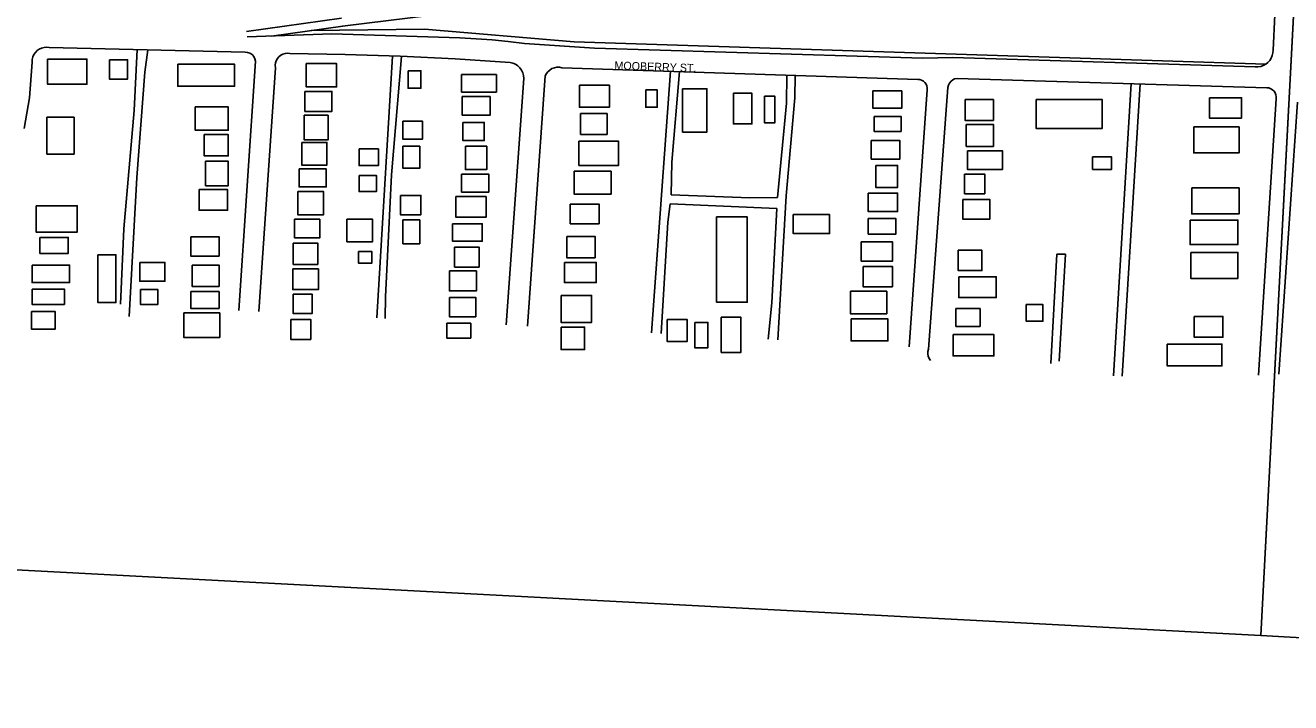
# Model space of a CAD drawing. Extents: x -9648 to 41057, y -12373 to 40276.
# Drawn here: x 15887 to 17468, y -6142 to -5297 of the extents above; entities that cross this region are included whole.
import ezdxf

# ---------------------------------------------------------------- set-up
doc = ezdxf.new("R2010")
doc.units = 0
doc.layers.add('SC_Scratch1', color=7, linetype='Continuous')
doc.layers.add('SH_Data', color=7, linetype='Continuous')

msp = doc.modelspace()

# ---------------------------------------------------------------- linework, layer by layer
at = {"layer": 'SC_Scratch1'}
for p, q in [((17431, -6058.5), (17512.2, -4520.7)), ((17512.2, -4520.7), (17431, -6058.5)), ((15846.2, -5974.8), (17431, -6058.5)), ((17431, -6058.5), (19015.8, -6142.2))]:
    msp.add_line(p, q, dxfattribs=at)
at = {"layer": 'SH_Data'}
for p, q in [((16506.5, -5270.2), (16283.5, -5297.6)), ((16282.3, -5287.7), (16163.3, -5304.3)), ((17446.1, -5327.7), (17448.5, -5283.5)), ((16164.3, -5311.1), (16270.1, -5307.3)), ((16283.7, -5297.6), (16194.8, -5310)), ((16385.7, -5301.6), (16244.2, -5303.1)), ((16270.1, -5307.3), (16430.1, -5312.1)), ((16573, -5317.2), (16385.7, -5301.6)), ((16430.1, -5312.1), (16450.3, -5313.3)), ((15902, -5328.2), (15904.6, -5326.4)), ((15904.6, -5326.4), (15907.5, -5325)), ((15907.5, -5325), (15910.7, -5324.1)), ((15910.7, -5324.1), (15913.9, -5323.8)), ((15913.9, -5323.8), (15917.1, -5324.1)), ((15917.1, -5324.1), (16161.7, -5330.3)), ((16026.7, -5326.9), (16023.3, -5402.9)), ((16036.5, -5354.9), (16040.3, -5327.2)), ((16450.3, -5313.3), (16470.5, -5314.9)), ((16470.5, -5314.9), (16490.6, -5316.8)), ((16490.6, -5316.8), (16510.7, -5319.1)), ((16510.7, -5319.1), (16598.5, -5325.1)), ((17436.9, -5345.1), (16573, -5317.2)), ((16598.5, -5325.1), (17008.7, -5337.5)), ((17445.9, -5331.1), (17446.1, -5327.7)), ((15892.5, -5387.1), (15895.5, -5342.5)), ((15895.5, -5342.5), (15895.7, -5339.3)), ((15895.7, -5339.3), (15896.5, -5336.1)), ((15896.5, -5336.1), (15897.9, -5333.2)), ((15897.9, -5333.2), (15899.7, -5330.5)), ((15899.7, -5330.5), (15902, -5328.2)), ((16174.7, -5341.3), (16154, -5652.6)), ((16161.7, -5330.3), (16164.8, -5330.5)), ((16164.8, -5330.5), (16167.8, -5331.5)), ((16167.8, -5331.5), (16170.4, -5333.2)), ((16170.4, -5333.2), (16172.5, -5335.5)), ((16172.5, -5335.5), (16174, -5338.3)), ((16174, -5338.3), (16174.7, -5341.3)), ((16199.5, -5346.5), (16199.8, -5343.6)), ((16199.8, -5343.6), (16200.7, -5340.8)), ((16200.7, -5340.8), (16202.2, -5338.2)), ((16202.2, -5338.2), (16204.1, -5335.9)), ((16204.1, -5335.9), (16206.4, -5334)), ((16206.4, -5334), (16209, -5332.6)), ((16209, -5332.6), (16211.8, -5331.8)), ((16211.8, -5331.8), (16214.7, -5331.5)), ((16214.7, -5331.5), (16217.7, -5331.7)), ((16217.7, -5331.7), (16286.6, -5333)), ((16286.6, -5333), (16355.4, -5335.3)), ((16345.9, -5335), (16326.5, -5661.9)), ((16344.7, -5483.1), (16357.1, -5335.4)), ((16355.4, -5335.3), (16424.2, -5338.6)), ((16424.2, -5338.6), (16492.9, -5342.9)), ((16492.9, -5342.9), (16496.4, -5343.7)), ((16496.4, -5343.7), (16499.7, -5345.1)), ((17008.7, -5337.5), (17046.1, -5336.9)), ((17046.1, -5336.9), (17423.9, -5348.5)), ((17436.9, -5345.1), (17439.6, -5343)), ((17439.6, -5343), (17441.9, -5340.5)), ((17441.9, -5340.5), (17443.7, -5337.6)), ((17443.7, -5337.6), (17445.1, -5334.4)), ((17445.1, -5334.4), (17445.9, -5331.1)), ((16026.5, -5486.7), (16036.5, -5354.9)), ((16179.1, -5653.9), (16199.7, -5349.5)), ((16199.7, -5349.5), (16199.5, -5346.5)), ((16499.7, -5345.1), (16502.7, -5347.1)), ((16502.7, -5347.1), (16505.2, -5349.6)), ((16505.2, -5349.6), (16507.3, -5352.6)), ((16507.3, -5352.6), (16508.8, -5355.8)), ((16508.8, -5355.8), (16509.7, -5359.3)), ((16509.7, -5359.3), (16509.9, -5362.9)), ((16536.7, -5359.7), (16514.5, -5672.1)), ((16538.2, -5356.9), (16536.7, -5359.7)), ((16540.2, -5354.5), (16538.2, -5356.9)), ((16542.5, -5352.4), (16540.2, -5354.5)), ((16545.2, -5350.7), (16542.5, -5352.4)), ((16548.2, -5349.6), (16545.2, -5350.7)), ((16551.2, -5349), (16548.2, -5349.6)), ((16554.4, -5349), (16551.2, -5349)), ((16557.5, -5349.5), (16554.4, -5349)), ((17002.1, -5364.3), (16557.5, -5349.5)), ((16693.3, -5354), (16669.6, -5680.6)), ((16704.7, -5354.4), (16694.9, -5467.3)), ((16838.3, -5393.7), (16838.7, -5358.9)), ((16848.5, -5387.1), (16848.9, -5359.2)), ((17423.9, -5348.5), (17427.3, -5348.5)), ((17427.3, -5348.5), (17430.7, -5347.9)), ((17430.7, -5347.9), (17433.9, -5346.8)), ((17433.9, -5346.8), (17436.9, -5345.1)), ((16509.9, -5362.9), (16487.8, -5670.7)), ((17004.6, -5364.4), (17002.1, -5364.3)), ((17007, -5365.1), (17004.6, -5364.4)), ((17009.2, -5366.3), (17007, -5365.1)), ((17011.1, -5367.9), (17009.2, -5366.3)), ((17012.6, -5369.9), (17011.1, -5367.9)), ((17013.6, -5372.2), (17012.6, -5369.9)), ((17014.1, -5374.6), (17013.6, -5372.2)), ((17014.1, -5377.1), (17014.1, -5374.6)), ((17039.9, -5374.1), (17015.7, -5700.9)), ((17040.6, -5371.3), (17039.9, -5374.1)), ((17041.9, -5368.7), (17040.6, -5371.3)), ((17043.8, -5366.5), (17041.9, -5368.7)), ((17046.1, -5364.7), (17043.8, -5366.5)), ((17048.2, -5363.4), (17046.1, -5364.7)), ((17051.5, -5362.9), (17048.2, -5363.4)), ((17438.3, -5374.5), (17051.5, -5362.9)), ((17268.7, -5369.4), (17246.9, -5734)), ((17257.7, -5734.5), (17280.1, -5369.8)), ((17440.9, -5374.8), (17438.3, -5374.5)), ((17443.3, -5375.7), (17440.9, -5374.8)), ((15885.7, -5425.5), (15892.5, -5387.1)), ((16837.7, -5509.3), (16848.5, -5387.1)), ((16991.3, -5698), (17014.1, -5377.1)), ((17427.9, -5733.5), (17450.1, -5388.5)), ((17445.5, -5377), (17443.3, -5375.7)), ((17447.4, -5378.8), (17445.5, -5377)), ((17448.9, -5380.9), (17447.4, -5378.8)), ((17449.8, -5383.4), (17448.9, -5380.9)), ((17450.2, -5385.9), (17449.8, -5383.4)), ((17450.1, -5388.5), (17450.2, -5385.9)), ((16023.3, -5402.9), (16010.3, -5550.5)), ((16827.1, -5511.7), (16838.3, -5393.7)), ((17453.5, -5732.3), (17476.5, -5392.7)), ((16694.9, -5467.3), (16693.9, -5508.3)), ((16337.3, -5635.5), (16344.7, -5483.1)), ((16017.1, -5660.3), (16026.5, -5486.7)), ((16693.9, -5508.3), (16792.3, -5512.1)), ((16792.3, -5512.1), (16827.1, -5511.7)), ((16827.3, -5689.1), (16837.7, -5509.3)), ((16690.1, -5542.3), (16692.7, -5519.5)), ((16692.7, -5519.5), (16826.3, -5525.1)), ((16826.3, -5525.1), (16819.9, -5643.1)), ((16681.5, -5681.2), (16690.1, -5542.3)), ((16010.3, -5550.5), (16006.2, -5644.6)), ((17175.9, -5582.1), (17168.3, -5718.7)), ((17186.7, -5582.1), (17175.9, -5582.1)), ((17178.7, -5715.7), (17186.7, -5582.1)), ((16336.6, -5662.5), (16337.3, -5635.5)), ((16819.9, -5643.1), (16815.2, -5688.5)), ((17014.9, -5703.8), (17014.8, -5706.8)), ((17014.8, -5706.8), (17015.3, -5709.8)), ((17015.7, -5700.9), (17014.9, -5703.8)), ((17015.3, -5709.8), (17016.5, -5712.5)), ((17016.5, -5712.5), (17018.3, -5714.9))]:
    msp.add_line(p, q, dxfattribs=at)
for points in [[(15915, -5338.8), (15964.1, -5338.8), (15964.1, -5370.2), (15915, -5370.2)], [(15992.3, -5339.6), (16014.9, -5339.6), (16014.9, -5363.8), (15992.3, -5363.8)], [(16077.7, -5345.3), (16148.7, -5345.3), (16148.7, -5372.7), (16077.7, -5372.7)], [(16238.1, -5344.4), (16276, -5344.4), (16276, -5373.5), (16238.1, -5373.5)], [(16365.4, -5353.3), (16381.5, -5353.3), (16381.5, -5375.1), (16365.4, -5375.1)], [(16432.3, -5358.2), (16475.8, -5358.2), (16475.8, -5379.9), (16432.3, -5379.9)], [(16579.5, -5371.4), (16617, -5371.4), (16617, -5398.8), (16579.5, -5398.8)], [(16236.5, -5379.1), (16270.3, -5379.1), (16270.3, -5404.1), (16236.5, -5404.1)], [(16433.1, -5385.6), (16467.8, -5385.6), (16467.8, -5408.9), (16433.1, -5408.9)], [(16662.3, -5377.2), (16676.7, -5377.2), (16676.7, -5398.8), (16662.3, -5398.8)], [(16708.4, -5375.7), (16738.7, -5375.7), (16738.7, -5429.8), (16708.4, -5429.8)], [(16771.8, -5381.5), (16794.9, -5381.5), (16794.9, -5419.7), (16771.8, -5419.7)], [(16810.7, -5385.1), (16823.7, -5385.1), (16823.7, -5418.2), (16810.7, -5418.2)], [(16946.1, -5378.6), (16982.2, -5378.6), (16982.2, -5400.2), (16946.1, -5400.2)], [(17061.4, -5389.4), (17096.7, -5389.4), (17096.7, -5415.4), (17061.4, -5415.4)], [(17150, -5389.4), (17232.8, -5389.4), (17232.8, -5425.4), (17150, -5425.4)], [(17366.6, -5387.1), (17406.8, -5387.1), (17406.8, -5412.5), (17366.6, -5412.5)], [(16099.5, -5398.5), (16140.6, -5398.5), (16140.6, -5427.5), (16099.5, -5427.5)], [(16581, -5406.7), (16614.1, -5406.7), (16614.1, -5432.7), (16581, -5432.7)], [(15914.2, -5411.4), (15948, -5411.4), (15948, -5457.3), (15914.2, -5457.3)], [(16235.7, -5408.9), (16265.5, -5408.9), (16265.5, -5439.6), (16235.7, -5439.6)], [(16359, -5416.2), (16383.2, -5416.2), (16383.2, -5438.8), (16359, -5438.8)], [(16433.9, -5417.8), (16460.5, -5417.8), (16460.5, -5440.4), (16433.9, -5440.4)], [(16947.6, -5410.3), (16981.4, -5410.3), (16981.4, -5429), (16947.6, -5429)], [(17062.8, -5420.4), (17096.7, -5420.4), (17096.7, -5447.8), (17062.8, -5447.8)], [(16110.8, -5433.1), (16140.6, -5433.1), (16140.6, -5459.7), (16110.8, -5459.7)], [(17347.1, -5423.5), (17403.6, -5423.5), (17403.6, -5456), (17347.1, -5456)], [(16232.5, -5442.8), (16263.9, -5442.8), (16263.9, -5471), (16232.5, -5471)], [(16304.2, -5450.9), (16328.4, -5450.9), (16328.4, -5471.8), (16304.2, -5471.8)], [(16359, -5447.6), (16379.9, -5447.6), (16379.9, -5475), (16359, -5475)], [(16437.1, -5447.6), (16463.7, -5447.6), (16463.7, -5476.7), (16437.1, -5476.7)], [(16578.8, -5441.3), (16628.5, -5441.3), (16628.5, -5471.6), (16578.8, -5471.6)], [(16944, -5440.6), (16980, -5440.6), (16980, -5463.6), (16944, -5463.6)], [(17064.3, -5453.5), (17108.2, -5453.5), (17108.2, -5476.6), (17064.3, -5476.6)], [(16112.4, -5466.2), (16140.6, -5466.2), (16140.6, -5496.8), (16112.4, -5496.8)], [(17220.6, -5460.8), (17244.3, -5460.8), (17244.3, -5476.6), (17220.6, -5476.6)], [(16229.2, -5475.8), (16263.1, -5475.8), (16263.1, -5498.4), (16229.2, -5498.4)], [(16304.2, -5483.9), (16325.9, -5483.9), (16325.9, -5504.1), (16304.2, -5504.1)], [(16432.3, -5482.3), (16466.2, -5482.3), (16466.2, -5504.9), (16432.3, -5504.9)], [(16573, -5478.8), (16619.1, -5478.8), (16619.1, -5507.6), (16573, -5507.6)], [(16949.7, -5471.6), (16977.1, -5471.6), (16977.1, -5498.9), (16949.7, -5498.9)], [(17060.7, -5482.4), (17085.9, -5482.4), (17085.9, -5506.9), (17060.7, -5506.9)], [(16104.3, -5501.6), (16139.8, -5501.6), (16139.8, -5527.4), (16104.3, -5527.4)], [(17344.5, -5499.6), (17403.6, -5499.6), (17403.6, -5532), (17344.5, -5532)], [(16227.6, -5504.1), (16259.9, -5504.1), (16259.9, -5533.1), (16227.6, -5533.1)], [(16355.8, -5508.9), (16381.5, -5508.9), (16381.5, -5533.1), (16355.8, -5533.1)], [(16425.1, -5510.5), (16462.9, -5510.5), (16462.9, -5536.3), (16425.1, -5536.3)], [(16940.4, -5506.1), (16977.1, -5506.1), (16977.1, -5529.2), (16940.4, -5529.2)], [(17058.5, -5514.1), (17092.4, -5514.1), (17092.4, -5538.6), (17058.5, -5538.6)], [(15900.5, -5521.8), (15952, -5521.8), (15952, -5554.8), (15900.5, -5554.8)], [(16568, -5519.8), (16604, -5519.8), (16604, -5544.3), (16568, -5544.3)], [(16846.7, -5532.8), (16892.1, -5532.8), (16892.1, -5556.6), (16846.7, -5556.6)], [(16223.6, -5538.7), (16255, -5538.7), (16255, -5562.1), (16223.6, -5562.1)], [(16288.9, -5538.7), (16321.1, -5538.7), (16321.1, -5566.9), (16288.9, -5566.9)], [(16359, -5539.5), (16379.9, -5539.5), (16379.9, -5569.4), (16359, -5569.4)], [(16421, -5544.4), (16458.1, -5544.4), (16458.1, -5566.1), (16421, -5566.1)], [(16750.9, -5535.7), (16789.1, -5535.7), (16789.1, -5642.3), (16750.9, -5642.3)], [(16940.4, -5537.8), (16974.9, -5537.8), (16974.9, -5557.3), (16940.4, -5557.3)], [(17342.5, -5539.8), (17402.3, -5539.8), (17402.3, -5570.4), (17342.5, -5570.4)], [(15905.3, -5561.3), (15940.7, -5561.3), (15940.7, -5581.4), (15905.3, -5581.4)], [(16093.9, -5560.5), (16129.3, -5560.5), (16129.3, -5584.7), (16093.9, -5584.7)], [(16563.7, -5560.2), (16599, -5560.2), (16599, -5586.8), (16563.7, -5586.8)], [(16222, -5568.5), (16252.6, -5568.5), (16252.6, -5595.1), (16222, -5595.1)], [(16303.4, -5579), (16320.3, -5579), (16320.3, -5593.5), (16303.4, -5593.5)], [(16423.4, -5573.4), (16454.1, -5573.4), (16454.1, -5598.4), (16423.4, -5598.4)], [(16931.7, -5566.7), (16970.6, -5566.7), (16970.6, -5591.2), (16931.7, -5591.2)], [(17052.7, -5577.5), (17082.3, -5577.5), (17082.3, -5602.7), (17052.7, -5602.7)], [(17343.2, -5580.1), (17402.3, -5580.1), (17402.3, -5612.6), (17343.2, -5612.6)], [(15895.6, -5596), (15942.4, -5596), (15942.4, -5617.7), (15895.6, -5617.7)], [(15977.8, -5583.1), (16000.4, -5583.1), (16000.4, -5642.7), (15977.8, -5642.7)], [(16030.2, -5592.7), (16061.6, -5592.7), (16061.6, -5616.1), (16030.2, -5616.1)], [(16095.5, -5596), (16129.3, -5596), (16129.3, -5622.6), (16095.5, -5622.6)], [(16560.8, -5592.6), (16600.4, -5592.6), (16600.4, -5617.8), (16560.8, -5617.8)], [(16221.2, -5600.8), (16253.4, -5600.8), (16253.4, -5626.6), (16221.2, -5626.6)], [(16417, -5603.2), (16450.8, -5603.2), (16450.8, -5628.2), (16417, -5628.2)], [(16933.9, -5597.7), (16970.6, -5597.7), (16970.6, -5622.9), (16933.9, -5622.9)], [(17053.5, -5610.6), (17100.3, -5610.6), (17100.3, -5636.6), (17053.5, -5636.6)], [(15895.6, -5625.8), (15935.9, -5625.8), (15935.9, -5645.1), (15895.6, -5645.1)], [(16031, -5626.6), (16052.8, -5626.6), (16052.8, -5645.1), (16031, -5645.1)], [(16093.9, -5629), (16129.3, -5629), (16129.3, -5650), (16093.9, -5650)], [(16222, -5632.2), (16245.4, -5632.2), (16245.4, -5656.4), (16222, -5656.4)], [(16417, -5636.3), (16450, -5636.3), (16450, -5660.4), (16417, -5660.4)], [(16556.5, -5633.7), (16594.6, -5633.7), (16594.6, -5667.5), (16556.5, -5667.5)], [(16918, -5628.6), (16963.4, -5628.6), (16963.4, -5656.7), (16918, -5656.7)], [(15894.8, -5654), (15924.6, -5654), (15924.6, -5675.8), (15894.8, -5675.8)], [(16085, -5655.6), (16130.1, -5655.6), (16130.1, -5686.2), (16085, -5686.2)], [(17049.9, -5650.3), (17080.1, -5650.3), (17080.1, -5672.6), (17049.9, -5672.6)], [(17137.7, -5645.2), (17158.6, -5645.2), (17158.6, -5666.1), (17137.7, -5666.1)], [(17347.7, -5660), (17383.5, -5660), (17383.5, -5686), (17347.7, -5686)], [(16218.8, -5663.7), (16243.7, -5663.7), (16243.7, -5688.7), (16218.8, -5688.7)], [(16413.8, -5668.5), (16443.6, -5668.5), (16443.6, -5687), (16413.8, -5687)], [(16556.5, -5673.3), (16586, -5673.3), (16586, -5701.4), (16556.5, -5701.4)], [(16689, -5663.9), (16714.2, -5663.9), (16714.2, -5691.3), (16689, -5691.3)], [(16723.6, -5667.5), (16740.1, -5667.5), (16740.1, -5699.2), (16723.6, -5699.2)], [(16756.7, -5661.1), (16781.2, -5661.1), (16781.2, -5705), (16756.7, -5705)], [(16918.8, -5663.2), (16964.9, -5663.2), (16964.9, -5690.6), (16918.8, -5690.6)], [(17046.3, -5682.7), (17097.4, -5682.7), (17097.4, -5709.3), (17046.3, -5709.3)], [(17314, -5694.5), (17382.2, -5694.5), (17382.2, -5721.8), (17314, -5721.8)]]:
    msp.add_lwpolyline(points, close=True, dxfattribs=at)

# ---------------------------------------------------------------- texts
at = {"layer": 'SC_Scratch1'}
msp.add_text('MOOBERRY ST.', height=10, rotation=358.0934, dxfattribs=at).set_placement((16623.1, -5351.6))

doc.saveas('drawing.dxf')
